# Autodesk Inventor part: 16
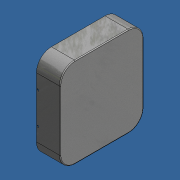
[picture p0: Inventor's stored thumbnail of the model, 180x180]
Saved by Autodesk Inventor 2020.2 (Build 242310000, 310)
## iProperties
Created: 2016-09
Part Number: 16
Material: Steel
Document SubType Name: Modeling
Designer: Mike Taylor
Mass: 1731.84 g
Surface Area: 2965.15 cm^2
Volume: 220.616 cm^3
Density: 7.85 g/cm^3
Appearance: Anodized - Gray
Translation Standard: STEP AP214IS
FileName: 29_5060_0_1.stp
PreProcessor: ACIS
PostProcessor: Build: 160, Release: 2012 RTM - Date: Tue 03/01/2011
Sent Units: centimeter
Uncertainty: 0.0
Author: Mike Taylor
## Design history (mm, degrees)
node "161"
node "16"
node "Base1"
